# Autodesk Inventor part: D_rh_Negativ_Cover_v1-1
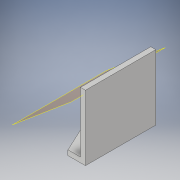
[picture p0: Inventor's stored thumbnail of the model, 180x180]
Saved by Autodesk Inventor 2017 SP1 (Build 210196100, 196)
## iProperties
Part Number: D_rh_Negativ_Cover_v1-1
Material: Generisch
Document SubType Name: Modeling
Designer: haesner
Density: 1 g/cm^3
Appearance: Vorgabe
Part Number: D_rh_Negativ_Cover_v1-1_3D-Druck
Author: haesner
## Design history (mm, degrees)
sketch "Skizze1"
  geometry: L1 (0, 14)-(0, -14); L2 (0, -19.6)-(0, 19.6) reference; L3 (0, 14)-(-18, 14); L4 (-18, 14)-(-4.943, -14); L5 (-4.943, -14)-(0, -14); L6 (-21.6, 0)-(3.6, 0) reference; 1 further point
  constraints: 8 end point, 1 collinear, 1 horizontal, 1 perpendicular, 1 vertical, 1 other
  dimensions: "d22" = 25 deg angle of L4 L1; "d23" = 18 distance of L1.start L3.end; "d24" = 28 distance of L1.start L1.end
extrude "Extrusion1" new body sketch "Skizze1" distance "d1" = 2; taper "d2" = 0 deg
sketch "Skizze2"
  geometry: L1 (0, -8.5)-(-1, -8.5); L2 (-1, -8.5)-(-8.927, 8.5); L3 (-8.927, 8.5)-(0, 8.5); L4 (0, -8.5)-(0, 8.5); L5 (-21.6, 0)-(3.6, 0) reference; L6 (0, -19.6)-(0, 19.6) reference; L7 (0, -14)-(0, 14) reference; 1 further point
  constraints: 8 end point, 1 collinear, 1 horizontal, 1 parallel, 1 perpendicular, 1 other
  dimensions: "d3" = 1 distance of L1.start L1.end; "d4" = 17 distance of L1.start L3.end; "d5" = 25 deg angle of L4 L2
extrude "Extrusion2" join sketch "Skizze2" distance "d6" = 21; taper "d7" = 0 deg
workplane "Arbeitsebene1"
feature "Trennen1"
sketch "Skizze3"
  geometry: L1 (0, 28)-(0, 0) reference; L2 (0, 28)-(-26, 28); L3 (-26, 28)-(-26, 0); L4 (-26, 0)-(0, 0); L5 (0, 0)-(0, 28); L6 (5.2, 14)-(-31.2, 14) reference; 1 further point
  constraints: 8 end point, 2 parallel, 1 horizontal, 1 perpendicular, 1 point on line, 1 other
  dimensions: "d9" = 28 distance between parallel lines of L2 L4; "d10" = 26 distance between parallel lines of L3 L1
extrude "Extrusion3" join sketch "Skizze3" distance "d11" = 2; taper "d12" = 0 deg
node "Volumenkörper1"
other parameters: "d8" = -40 deg
